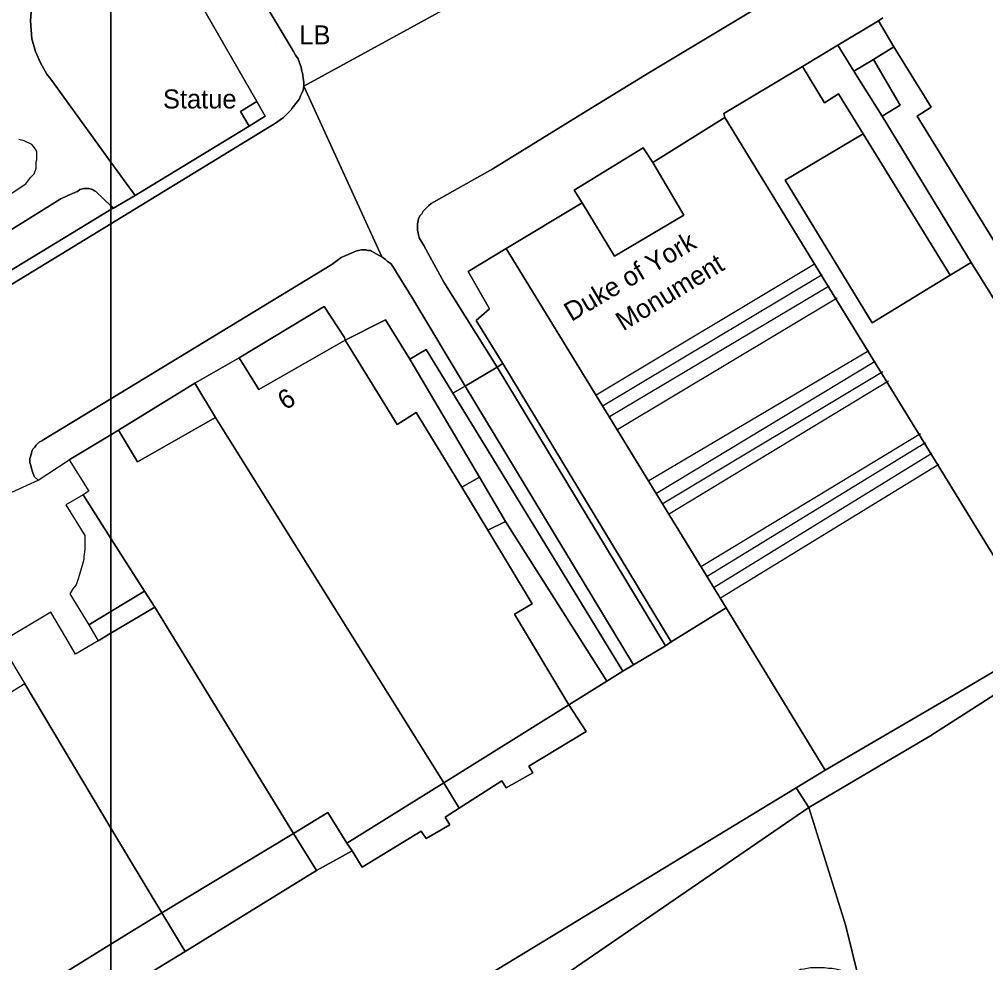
# Model space of a CAD drawing. Extents: x 529240 to 530363, y 179600 to 180767.
# Drawn here: x 529708.8 to 529784.9, y 180192.1 to 180266.5 of the extents above; entities that cross this region are included whole.
import ezdxf

# ---------------------------------------------------------------- set-up
doc = ezdxf.new("R2010")
doc.units = 0
for name, color, linetype in [('Building', 7, 'Continuous'), ('General surface', 7, 'Continuous'), ('Natural environment', 7, 'Continuous'), ('Path', 7, 'Continuous'), ('Road Or Track', 7, 'Continuous'), ('Roadside', 7, 'Continuous'), ('Structure', 7, 'Continuous'), ('Unclassified', 7, 'Continuous')]:
    doc.layers.add(name, color=color, linetype=linetype)

msp = doc.modelspace()

# ---------------------------------------------------------------- linework, layer by layer
at = {"layer": 'Building'}
for points in [[(529776.85, 180266.6), (529776.5, 180266.35), (529777.7, 180264.3), (529780.65, 180259.55), (529779.55, 180258.85), (529788.6, 180244.15)], [(529776.85, 180266.6), (529776.5, 180266.35)], [(529777.7, 180264.3), (529776.5, 180266.35)], [(529794, 180237.65), (529789.6, 180244.8), (529788.6, 180244.15), (529779.55, 180258.85), (529780.65, 180259.55), (529777.7, 180264.3)], [(529782.15, 180246.3), (529776, 180242.55), (529769.15, 180253.8), (529775.3, 180257.45)], [(529775.3, 180257.45), (529782.15, 180246.3)], [(529734.45, 180241.2), (529727.65, 180237.3), (529726.1, 180239.8)], [(529734.45, 180241.2), (529734.4, 180241.4)], [(529734.45, 180241.2), (529738.55, 180234.55), (529740.05, 180235.5), (529743.65, 180229.6)], [(529726.1, 180239.8), (529722.6, 180237.8)], [(529722.6, 180237.8), (529724.25, 180235.1)], [(529724.25, 180235.1), (529718.1, 180231.6), (529716.6, 180234.1)], [(529724.25, 180235.1), (529742.25, 180206.3)], [(529716.6, 180234.1), (529716, 180233.738)], [(529716, 180233.738), (529712.7, 180231.75)], [(529743.65, 180229.6), (529745.7, 180226.2)], [(529713.8, 180229), (529716, 180225.553)], [(529716, 180225.553), (529718.65, 180221.4)], [(529745.7, 180226.2), (529749.2, 180220.4), (529747.8, 180219.6), (529752.1, 180212.45)], [(529716, 180219.804), (529718.65, 180221.4)], [(529718.65, 180221.4), (529719.45, 180220.15)], [(529719.45, 180220.15), (529716, 180218.096)], [(529719.45, 180220.15), (529730.4, 180202.3)], [(529714.25, 180218.75), (529716, 180219.804)], [(529716, 180218.096), (529715, 180217.5)], [(529709.2, 180214.1), (529716, 180202.735)], [(529752.1, 180212.45), (529742.25, 180206.3)], [(529742.25, 180206.3), (529734.6, 180201.55)], [(529734.6, 180201.55), (529733.1, 180203.95), (529730.4, 180202.3)], [(529716, 180202.735), (529720, 180196.05)], [(529730.4, 180202.3), (529720, 180196.05)], [(529730.4, 180202.3), (529732.2, 180199.4)], [(529735, 180200.95), (529734.6, 180201.55)], [(529735, 180200.95), (529732.2, 180199.4)], [(529732.2, 180199.4), (529721.85, 180193)], [(529720, 180196.05), (529716, 180193.578)], [(529720, 180196.05), (529721.85, 180193)], [(529716, 180193.578), (529707.3, 180188.2)], [(529721.85, 180193), (529716, 180189.421)]]:
    msp.add_lwpolyline(points, dxfattribs=at)
for points in [[(529782.15, 180246.3), (529775.3, 180257.45), (529769.15, 180253.8), (529776, 180242.55)], [(529745.7, 180226.2), (529743.65, 180229.6), (529740.05, 180235.5), (529738.55, 180234.55), (529734.45, 180241.2), (529727.65, 180237.3), (529726.1, 180239.8), (529722.6, 180237.8), (529724.25, 180235.1), (529742.25, 180206.3), (529752.1, 180212.45), (529747.8, 180219.6), (529749.2, 180220.4)], [(529716, 180225.553), (529718.65, 180221.4), (529719.45, 180220.15), (529730.4, 180202.3), (529733.1, 180203.95), (529734.6, 180201.55), (529742.25, 180206.3), (529724.25, 180235.1), (529718.1, 180231.6), (529716.6, 180234.1), (529716, 180233.738)], [(529716, 180225.553), (529716, 180233.738), (529712.7, 180231.75), (529714.25, 180229.3), (529713.8, 180229)], [(529716, 180218.096), (529719.45, 180220.15), (529718.65, 180221.4), (529716, 180219.804)], [(529716, 180202.735), (529720, 180196.05), (529730.4, 180202.3), (529719.45, 180220.15), (529716, 180218.096)], [(529716, 180202.735), (529716, 180218.096), (529715, 180217.5), (529713.2, 180216.45), (529712.45, 180217.75), (529711.25, 180219.75), (529707.25, 180217.35), (529707.45, 180217.05), (529709.2, 180214.1)], [(529716, 180218.096), (529716, 180219.804), (529714.25, 180218.75), (529715, 180217.5)], [(529716, 180193.578), (529716, 180202.735), (529709.2, 180214.1), (529706.65, 180212.55), (529704.8, 180215.45), (529704.55, 180215.8), (529700.4, 180213.2), (529701.7, 180211.15), (529702.45, 180210), (529696.3, 180206.1), (529707.3, 180188.2)], [(529730.4, 180202.3), (529732.2, 180199.4), (529735, 180200.95), (529734.6, 180201.55), (529733.1, 180203.95)], [(529716, 180193.578), (529720, 180196.05), (529716, 180202.735)], [(529721.85, 180193), (529732.2, 180199.4), (529730.4, 180202.3), (529720, 180196.05)], [(529716, 180189.421), (529721.85, 180193), (529720, 180196.05), (529716, 180193.578)], [(529716, 180189.421), (529716, 180193.578), (529707.3, 180188.2), (529709.1, 180185.2)]]:
    msp.add_lwpolyline(points, close=True, dxfattribs=at)
at = {"layer": 'General surface'}
for points in [[(529776.5, 180266.35), (529773.3, 180264.45), (529774.55, 180262.4), (529776.1, 180263.3), (529777.7, 180264.3)], [(529775.3, 180257.45), (529782.15, 180246.3), (529783.8, 180247.3), (529776.8, 180258.85), (529774.55, 180262.4), (529773.3, 180264.45), (529770.5, 180262.75), (529772.25, 180259.9), (529773.35, 180260.6)], [(529795.1, 180235.6), (529794, 180237.65), (529789.6, 180244.8), (529788.6, 180244.15), (529779.55, 180258.85), (529780.65, 180259.55), (529777.7, 180264.3), (529776.1, 180263.3), (529778.2, 180259.7), (529776.8, 180258.85), (529783.8, 180247.3), (529790.55, 180236.45), (529792.15, 180237.3), (529793.8, 180234.85)], [(529776.1, 180263.3), (529774.55, 180262.4), (529776.8, 180258.85), (529778.2, 180259.7)], [(529734.45, 180241.2), (529734.4, 180241.4), (529732.8, 180243.85), (529726.1, 180239.8), (529727.65, 180237.3)], [(529737.65, 180242.8), (529734.45, 180241.2), (529738.55, 180234.55), (529740.05, 180235.5), (529743.65, 180229.6), (529745.05, 180230.4), (529739.55, 180239.7)], [(529743.93, 180237.57), (529757.2, 180215.6), (529759.7, 180217.1), (529746.45, 180239.07)], [(529722.6, 180237.8), (529716.6, 180234.1), (529718.1, 180231.6), (529724.25, 180235.1)], [(529747.1, 180226.9), (529745.05, 180230.4), (529743.65, 180229.6), (529745.7, 180226.2)], [(529716, 180219.804), (529716, 180225.553), (529713.8, 180229), (529712.45, 180228.2), (529713.95, 180225.8), (529713.95, 180224.7), (529713.85, 180224.15), (529713.85, 180223.9), (529713.55, 180222.8), (529713.4, 180222.3), (529713.25, 180221.9), (529713, 180221.6), (529712.75, 180221.2), (529714.25, 180218.75)], [(529745.7, 180226.2), (529749.2, 180220.4), (529747.8, 180219.6), (529752.1, 180212.45), (529755.1, 180214.3), (529747.1, 180226.9)], [(529716, 180219.804), (529718.65, 180221.4), (529716, 180225.553)], [(529772.3, 180207.3), (529770, 180205.9), (529771, 180204.35), (529780.55, 180209.98), (529792.04, 180217.33), (529795.6, 180213.47), (529800.09, 180209.09), (529800, 180209.4), (529799.85, 180209.7), (529799.55, 180210.6), (529799.5, 180210.85), (529799.5, 180211.55), (529799.55, 180211.75), (529799.6, 180212), (529799.8, 180212.5), (529805.55, 180216.7), (529801.05, 180224.3), (529798.35, 180222.65), (529789.7, 180217.5), (529782.39, 180213.19)], [(529752.1, 180212.45), (529742.25, 180206.3), (529743.45, 180204.3), (529746.8, 180206.45), (529747.15, 180205.9), (529749.25, 180207.1), (529748.95, 180207.6), (529753.45, 180210.35)], [(529716, 180166.623), (529771, 180204.35), (529770, 180205.9), (529739.62, 180187.44), (529729.1, 180181.05), (529716.27, 180173.25), (529716, 180173.086)], [(529743.45, 180204.3), (529742.25, 180206.3), (529734.6, 180201.55), (529735, 180200.95), (529735.8, 180199.65), (529740.45, 180202.5), (529740.85, 180201.9), (529742.7, 180203), (529742.35, 180203.6)], [(529716, 180166.623), (529716, 180154.06), (529749.3, 180177.15), (529770.35, 180191.6), (529770.65, 180191.65), (529771.15, 180191.75), (529772.25, 180191.75), (529772.55, 180191.7), (529772.85, 180191.7), (529773.15, 180191.65), (529773.45, 180191.55), (529773.55, 180191.5), (529773.85, 180191.4), (529774.35, 180191.1), (529774.99, 180190.74), (529773.91, 180195.12), (529771, 180204.35)]]:
    msp.add_lwpolyline(points, close=True, dxfattribs=at)
for points in [[(529790.55, 180236.45), (529783.8, 180247.3), (529782.15, 180246.3), (529776, 180242.55), (529769.15, 180253.8), (529775.3, 180257.45), (529773.35, 180260.6), (529772.25, 180259.9), (529770.5, 180262.75), (529764.3, 180259.05), (529764.4, 180258.75), (529773.15, 180244.45), (529781.2, 180231.3), (529789.7, 180217.5)], [(529739.62, 180187.44), (529770, 180205.9), (529772.3, 180207.3), (529764.5, 180220.1), (529760.15, 180217.4), (529759.7, 180217.1), (529757.2, 180215.6), (529756.35, 180215.1), (529755.1, 180214.3), (529752.1, 180212.45), (529753.45, 180210.35), (529748.95, 180207.6), (529749.25, 180207.1), (529747.15, 180205.9), (529746.8, 180206.45), (529743.45, 180204.3), (529742.35, 180203.6), (529742.7, 180203), (529740.85, 180201.9), (529740.45, 180202.5), (529735.8, 180199.65), (529735, 180200.95), (529732.2, 180199.4), (529721.85, 180193), (529716, 180189.421)]]:
    msp.add_lwpolyline(points, dxfattribs=at)
at = {"layer": 'Natural environment'}
for points in [[(529709.7, 180267.05), (529709.65, 180266.35), (529709.75, 180264.95), (529710.05, 180263.95), (529710.45, 180263.05), (529710.95, 180262.15), (529711.25, 180261.75), (529716, 180255.214), (529716, 180275.918)], [(529686.9, 180233.8), (529716, 180251.478), (529716, 180251.786), (529714.8, 180252.9), (529714.7, 180252.95), (529714.55, 180253.05), (529714.25, 180253.15), (529713.85, 180253.15), (529713.55, 180253.05), (529713.35, 180252.9), (529713.2, 180252.85), (529713.1, 180252.8), (529712.6, 180252.6), (529712, 180252.3), (529709.05, 180250.45), (529687, 180236.95)]]:
    msp.add_lwpolyline(points, dxfattribs=at)
for points in [[(529716, 180255.214), (529717.9, 180252.6), (529726.9, 180258.05), (529726.2, 180259.2), (529727.5, 180260), (529718.9, 180274.95), (529717.2, 180273.95), (529716, 180275.918)], [(529716, 180251.478), (529716.2, 180251.6), (529716, 180251.786)]]:
    msp.add_lwpolyline(points, close=True, dxfattribs=at)
at = {"layer": 'Path'}
for points in [[(529687, 180236.95), (529709.05, 180250.45), (529712, 180252.3), (529712.6, 180252.6), (529713.1, 180252.8), (529713.2, 180252.85), (529713.35, 180252.9), (529713.55, 180253.05), (529713.85, 180253.15), (529714.25, 180253.15), (529714.55, 180253.05), (529714.7, 180252.95), (529714.8, 180252.9), (529716, 180251.786), (529716, 180255.214), (529711.25, 180261.75), (529710.95, 180262.15), (529710.45, 180263.05), (529710.05, 180263.95), (529709.75, 180264.95), (529709.65, 180266.35), (529709.7, 180267.05)], [(529706.6, 180251.75), (529709.3, 180253.5), (529709.65, 180254), (529709.95, 180254.3), (529710.1, 180254.75), (529710.1, 180255.25), (529710.15, 180255.4), (529710.15, 180256), (529710.1, 180256.15), (529709.9, 180256.45), (529709.75, 180256.6), (529709.15, 180256.9), (529708.75, 180257)]]:
    msp.add_lwpolyline(points, dxfattribs=at)
for points in [[(529716, 180251.786), (529716.2, 180251.6), (529717.9, 180252.6), (529716, 180255.214)], [(529746.45, 180239.07), (529759.7, 180217.1), (529760.15, 180217.4), (529746.9, 180239.35)], [(529742.95, 180237), (529746.45, 180231.3), (529756.35, 180215.1), (529757.2, 180215.6), (529743.93, 180237.57)]]:
    msp.add_lwpolyline(points, close=True, dxfattribs=at)
at = {"layer": 'Road Or Track'}
for points in [[(529716, 180288.42), (529716.45, 180287.5), (529717.65, 180285.2), (529730.2, 180264.25), (529730.4, 180263.95), (529730.55, 180263.65), (529730.75, 180263.35), (529730.85, 180263.05), (529731, 180262.7), (529731.05, 180262.35), (529731.1, 180262.25), (529731.15, 180261.85), (529731.2, 180261.5), (529731.2, 180261.2), (529746.35, 180269.5), (529746.2, 180269.55), (529746, 180269.65), (529745.85, 180269.8), (529745.75, 180269.95), (529732.4, 180292.4), (529731.05, 180291.55), (529727.65, 180297.5), (529728.85, 180298.25), (529716, 180320.312)], [(529716, 180236.572), (529733.4, 180247.15), (529734.15, 180247.7), (529735.3, 180248.2), (529735.5, 180248.25), (529735.75, 180248.3), (529736.1, 180248.3), (529736.25, 180248.25), (529736.45, 180248.25), (529736.55, 180248.2), (529737.1, 180247.9), (529737.35, 180247.75), (529731.2, 180261.2), (529731.15, 180260.9), (529731.05, 180260.65), (529730.95, 180260.45), (529730.85, 180260.2), (529730.4, 180259.6), (529730.25, 180259.45), (529730.2, 180259.35), (529729.6, 180258.75), (529728.9, 180258.25), (529728.5, 180258), (529716, 180250.359)]]:
    msp.add_lwpolyline(points, close=True, dxfattribs=at)
for points in [[(529716, 180288.42), (529716.45, 180287.5), (529717.65, 180285.2), (529730.2, 180264.25), (529730.4, 180263.95), (529730.55, 180263.65), (529730.75, 180263.35), (529730.85, 180263.05), (529731, 180262.7), (529731.05, 180262.35), (529731.1, 180262.25), (529731.15, 180261.85), (529731.2, 180261.5), (529731.2, 180261.2)], [(529746.35, 180269.5), (529731.2, 180261.2), (529737.35, 180247.75), (529737.65, 180247.55), (529737.8, 180247.4), (529738.1, 180247.2), (529739.8, 180244.45), (529743.93, 180237.57), (529746.45, 180239.07), (529742.25, 180245.75), (529740.65, 180248.65), (529740.3, 180249.25), (529740.15, 180249.85), (529740.15, 180250.35), (529740.25, 180250.75), (529740.35, 180251), (529740.5, 180251.15), (529740.6, 180251.35), (529741.05, 180251.8), (529741.25, 180251.95), (529746.1, 180254.7), (529752.14, 180258.41), (529753.52, 180259.26), (529758.4, 180262.25), (529767.85, 180267.93)], [(529767.85, 180267.93), (529758.4, 180262.25), (529753.52, 180259.26), (529752.14, 180258.41), (529746.1, 180254.7), (529741.25, 180251.95), (529741.05, 180251.8), (529740.6, 180251.35), (529740.5, 180251.15), (529740.35, 180251), (529740.25, 180250.75), (529740.15, 180250.35), (529740.15, 180249.85), (529740.3, 180249.25), (529740.65, 180248.65), (529742.25, 180245.75)], [(529731.2, 180261.2), (529731.15, 180260.9), (529731.05, 180260.65), (529730.95, 180260.45), (529730.85, 180260.2), (529730.4, 180259.6), (529730.25, 180259.45), (529730.2, 180259.35), (529729.6, 180258.75), (529728.9, 180258.25), (529728.5, 180258), (529716, 180250.359)], [(529716, 180250.359), (529712.55, 180248.25), (529676.85, 180226.5), (529651.05, 180210.85), (529650.75, 180210.55), (529650.55, 180210.45), (529650.3, 180210.35), (529650.2, 180210.3), (529649.95, 180210.25), (529649.75, 180210.15), (529649.5, 180210.15)], [(529706.95, 180228.65), (529710.25, 180230.15), (529709.95, 180230.45), (529709.8, 180230.9), (529709.75, 180231), (529709.65, 180231.4), (529709.6, 180231.55), (529709.6, 180231.85), (529709.65, 180232), (529709.7, 180232.2), (529709.8, 180232.5), (529709.85, 180232.6), (529710, 180232.75), (529710.1, 180232.9), (529710.35, 180233.15), (529710.55, 180233.25), (529710.7, 180233.35), (529716, 180236.572), (529716, 180250.359), (529712.55, 180248.25), (529676.85, 180226.5)], [(529737.35, 180247.75), (529737.1, 180247.9), (529736.55, 180248.2), (529736.45, 180248.25), (529736.25, 180248.25), (529736.1, 180248.3), (529735.75, 180248.3), (529735.5, 180248.25), (529735.3, 180248.2), (529734.15, 180247.7), (529733.4, 180247.15), (529716, 180236.572)], [(529739.8, 180244.45), (529738.1, 180247.2), (529737.8, 180247.4), (529737.65, 180247.55), (529737.35, 180247.75)], [(529716, 180236.572), (529710.7, 180233.35), (529710.55, 180233.25), (529710.35, 180233.15), (529710.1, 180232.9), (529710, 180232.75), (529709.85, 180232.6), (529709.8, 180232.5), (529709.7, 180232.2), (529709.65, 180232), (529709.6, 180231.85), (529709.6, 180231.55), (529709.65, 180231.4), (529709.75, 180231), (529709.8, 180230.9), (529709.95, 180230.45), (529710.25, 180230.15)], [(529792.04, 180217.33), (529780.55, 180209.98), (529771, 180204.35), (529773.91, 180195.12), (529774.99, 180190.74)], [(529771, 180204.35), (529780.55, 180209.98), (529792.04, 180217.33), (529795.6, 180213.47), (529800.09, 180209.09)], [(529774.99, 180190.74), (529773.91, 180195.12), (529771, 180204.35)]]:
    msp.add_lwpolyline(points, dxfattribs=at)
at = {"layer": 'Roadside'}
for points in [[(529718.9, 180274.95), (529727.5, 180260), (529728.15, 180258.85), (529726.9, 180258.05), (529717.9, 180252.6), (529716.2, 180251.6), (529716, 180251.478), (529716, 180250.359), (529728.5, 180258), (529728.9, 180258.25), (529729.6, 180258.75), (529730.2, 180259.35), (529730.25, 180259.45), (529730.4, 180259.6), (529730.85, 180260.2), (529730.95, 180260.45), (529731.05, 180260.65), (529731.15, 180260.9), (529731.2, 180261.2), (529731.2, 180261.5), (529731.15, 180261.85), (529731.1, 180262.25), (529731.05, 180262.35), (529731, 180262.7), (529730.85, 180263.05), (529730.75, 180263.35), (529730.55, 180263.65), (529730.4, 180263.95), (529730.2, 180264.25), (529717.65, 180285.2)], [(529767.85, 180267.93), (529758.4, 180262.25), (529753.52, 180259.26), (529752.14, 180258.41), (529746.1, 180254.7), (529741.25, 180251.95), (529741.05, 180251.8), (529740.6, 180251.35), (529740.5, 180251.15), (529740.35, 180251), (529740.25, 180250.75), (529740.15, 180250.35), (529740.15, 180249.85), (529740.3, 180249.25), (529740.65, 180248.65), (529742.25, 180245.75), (529746.45, 180239.07), (529746.9, 180239.35), (529744.8, 180242.75), (529745.85, 180243.65), (529744.15, 180246.6), (529747.15, 180248.4), (529753.15, 180252), (529752.5, 180253), (529757.95, 180256.35), (529758.7, 180255.2), (529764.4, 180258.75), (529764.3, 180259.05), (529770.5, 180262.75), (529773.3, 180264.45), (529776.5, 180266.35), (529776.85, 180266.6)], [(529651.05, 180210.85), (529676.85, 180226.5), (529712.55, 180248.25), (529716, 180250.359), (529716, 180251.478), (529686.9, 180233.8), (529685.65, 180233.05), (529654.9, 180214.4)]]:
    msp.add_lwpolyline(points, dxfattribs=at)
for points in [[(529746.9, 180239.35), (529760.15, 180217.4), (529764.5, 180220.1), (529747.15, 180248.4), (529744.15, 180246.6), (529745.85, 180243.65), (529744.8, 180242.75)], [(529716, 180233.738), (529716.6, 180234.1), (529722.6, 180237.8), (529726.1, 180239.8), (529732.8, 180243.85), (529734.4, 180241.4), (529734.45, 180241.2), (529737.65, 180242.8), (529739.55, 180239.7), (529740.85, 180240.45), (529742.95, 180237), (529743.93, 180237.57), (529739.8, 180244.45), (529738.1, 180247.2), (529737.8, 180247.4), (529737.65, 180247.55), (529737.35, 180247.75), (529737.1, 180247.9), (529736.55, 180248.2), (529736.45, 180248.25), (529736.25, 180248.25), (529736.1, 180248.3), (529735.75, 180248.3), (529735.5, 180248.25), (529735.3, 180248.2), (529734.15, 180247.7), (529733.4, 180247.15), (529716, 180236.572)], [(529745.05, 180230.4), (529747.1, 180226.9), (529755.1, 180214.3), (529756.35, 180215.1), (529746.45, 180231.3), (529742.95, 180237), (529740.85, 180240.45), (529739.55, 180239.7)], [(529716, 180233.738), (529716, 180236.572), (529710.7, 180233.35), (529710.55, 180233.25), (529710.35, 180233.15), (529710.1, 180232.9), (529710, 180232.75), (529709.85, 180232.6), (529709.8, 180232.5), (529709.7, 180232.2), (529709.65, 180232), (529709.6, 180231.85), (529709.6, 180231.55), (529709.65, 180231.4), (529709.75, 180231), (529709.8, 180230.9), (529709.95, 180230.45), (529710.25, 180230.15), (529710.95, 180230.6), (529712.7, 180231.75)]]:
    msp.add_lwpolyline(points, close=True, dxfattribs=at)
at = {"layer": 'Structure'}
msp.add_line((529729, 180264.3), (529729, 180264.3), dxfattribs=at)
for points in [[(529726.9, 180258.05), (529728.15, 180258.85), (529727.5, 180260), (529726.2, 180259.2)], [(529789.7, 180217.5), (529781.2, 180231.3), (529773.15, 180244.45), (529764.4, 180258.75), (529758.7, 180255.2), (529761.15, 180251.05), (529755.7, 180247.8), (529753.15, 180252), (529747.15, 180248.4), (529764.5, 180220.1), (529772.3, 180207.3), (529782.39, 180213.19)], [(529758.7, 180255.2), (529757.95, 180256.35), (529752.5, 180253), (529753.15, 180252), (529755.7, 180247.8), (529761.15, 180251.05)]]:
    msp.add_lwpolyline(points, close=True, dxfattribs=at)
at = {"layer": 'Unclassified'}
for points in [[(529727.5, 180260), (529718.9, 180274.95)], [(529746.35, 180269.5), (529731.2, 180261.2)], [(529709.7, 180267.05), (529709.65, 180266.35), (529709.75, 180264.95), (529710.05, 180263.95), (529710.45, 180263.05), (529710.95, 180262.15), (529711.25, 180261.75), (529716, 180255.214)], [(529776.5, 180266.35), (529773.3, 180264.45)], [(529773.3, 180264.45), (529770.5, 180262.75)], [(529774.55, 180262.4), (529773.3, 180264.45)], [(529776.1, 180263.3), (529777.7, 180264.3)], [(529774.55, 180262.4), (529776.1, 180263.3)], [(529776.1, 180263.3), (529778.2, 180259.7), (529776.8, 180258.85)], [(529770.5, 180262.75), (529764.3, 180259.05), (529764.4, 180258.75)], [(529770.5, 180262.75), (529772.25, 180259.9), (529773.35, 180260.6), (529775.3, 180257.45)], [(529776.8, 180258.85), (529774.55, 180262.4)], [(529737.35, 180247.75), (529731.2, 180261.2)], [(529727.5, 180260), (529726.2, 180259.2), (529726.9, 180258.05)], [(529726.9, 180258.05), (529728.15, 180258.85), (529727.5, 180260)], [(529764.4, 180258.75), (529758.7, 180255.2)], [(529789.7, 180217.5), (529781.2, 180231.3), (529773.15, 180244.45), (529764.4, 180258.75)], [(529783.8, 180247.3), (529776.8, 180258.85)], [(529717.9, 180252.6), (529726.9, 180258.05)], [(529758.7, 180255.2), (529757.95, 180256.35), (529752.5, 180253), (529753.15, 180252)], [(529716, 180255.214), (529717.9, 180252.6)], [(529753.15, 180252), (529755.7, 180247.8), (529761.15, 180251.05), (529758.7, 180255.2)], [(529716, 180251.786), (529714.8, 180252.9), (529714.7, 180252.95), (529714.55, 180253.05), (529714.25, 180253.15), (529713.85, 180253.15), (529713.55, 180253.05), (529713.35, 180252.9), (529713.2, 180252.85), (529713.1, 180252.8), (529712.6, 180252.6), (529712, 180252.3), (529709.05, 180250.45), (529687, 180236.95)], [(529716.2, 180251.6), (529717.9, 180252.6)], [(529686.9, 180233.8), (529716, 180251.478)], [(529716.2, 180251.6), (529716, 180251.786)], [(529716, 180251.478), (529716.2, 180251.6)], [(529753.15, 180252), (529747.15, 180248.4)], [(529747.15, 180248.4), (529744.15, 180246.6)], [(529764.5, 180220.1), (529747.15, 180248.4)], [(529771.5, 180247.2), (529754.25, 180236.85)], [(529782.15, 180246.3), (529783.8, 180247.3)], [(529795.1, 180235.6), (529793.8, 180234.85), (529792.15, 180237.3), (529790.55, 180236.45), (529783.8, 180247.3)], [(529744.15, 180246.6), (529745.85, 180243.65), (529744.8, 180242.75), (529746.9, 180239.35)], [(529772.05, 180246.35), (529754.8, 180236)], [(529742.25, 180245.75), (529746.45, 180239.07)], [(529772.6, 180245.45), (529755.3, 180235.15)], [(529734.4, 180241.4), (529732.8, 180243.85), (529726.1, 180239.8)], [(529743.93, 180237.57), (529739.8, 180244.45)], [(529773.25, 180244.5), (529755.95, 180234.15)], [(529737.65, 180242.8), (529734.45, 180241.2)], [(529737.65, 180242.8), (529739.55, 180239.7)], [(529739.55, 180239.7), (529740.85, 180240.45), (529742.95, 180237)], [(529775.75, 180240.35), (529758.4, 180230.1)], [(529739.55, 180239.7), (529745.05, 180230.4)], [(529746.45, 180239.07), (529746.9, 180239.35)], [(529746.9, 180239.35), (529760.15, 180217.4)], [(529776.25, 180239.5), (529759, 180229.1)], [(529743.93, 180237.57), (529746.45, 180239.07)], [(529746.45, 180239.07), (529759.7, 180217.1)], [(529776.85, 180238.7), (529759.45, 180228.25)], [(529722.6, 180237.8), (529716.6, 180234.1)], [(529777.3, 180237.95), (529759.95, 180227.45)], [(529742.95, 180237), (529743.93, 180237.57)], [(529742.95, 180237), (529746.45, 180231.3), (529756.35, 180215.1)], [(529757.2, 180215.6), (529743.93, 180237.57)], [(529779.8, 180233.8), (529762.55, 180223.35)], [(529780.2, 180233.1), (529763, 180222.55)], [(529780.7, 180232.25), (529763.55, 180221.7)], [(529781.25, 180231.4), (529764.05, 180220.85)], [(529743.65, 180229.6), (529745.05, 180230.4)], [(529745.05, 180230.4), (529747.1, 180226.9)], [(529745.7, 180226.2), (529747.1, 180226.9)], [(529747.1, 180226.9), (529755.1, 180214.3)], [(529764.5, 180220.1), (529760.15, 180217.4)], [(529772.3, 180207.3), (529764.5, 180220.1)], [(529760.15, 180217.4), (529759.7, 180217.1)], [(529772.3, 180207.3), (529782.39, 180213.19), (529789.7, 180217.5)], [(529759.7, 180217.1), (529757.2, 180215.6)], [(529757.2, 180215.6), (529756.35, 180215.1)], [(529756.35, 180215.1), (529755.1, 180214.3)], [(529755.1, 180214.3), (529752.1, 180212.45)], [(529752.1, 180212.45), (529753.45, 180210.35), (529748.95, 180207.6), (529749.25, 180207.1), (529747.15, 180205.9), (529746.8, 180206.45), (529743.45, 180204.3)], [(529770, 180205.9), (529772.3, 180207.3)], [(529716, 180173.086), (529716.27, 180173.25), (529729.1, 180181.05), (529739.62, 180187.44), (529770, 180205.9)], [(529742.25, 180206.3), (529743.45, 180204.3)], [(529770, 180205.9), (529771, 180204.35)], [(529771, 180204.35), (529716, 180166.623)], [(529743.45, 180204.3), (529742.35, 180203.6), (529742.7, 180203), (529740.85, 180201.9), (529740.45, 180202.5), (529735.8, 180199.65), (529735, 180200.95)]]:
    msp.add_lwpolyline(points, dxfattribs=at)

# ---------------------------------------------------------------- texts
at = {"layer": 'Structure'}
for s, p in [('LB', (529730.85, 180264.5)), ('Statue', (529720.1, 180259.45))]:
    msp.add_text(s, height=1.5, dxfattribs=at).set_placement(p)
for s, rotation, p in [('Duke of York', 30.6, (529752.29, 180242.62)), ('Monument', 31.3, (529756.38, 180241.87))]:
    msp.add_text(s, height=1.5, rotation=rotation, dxfattribs=at).set_placement(p)
at = {"layer": 'Unclassified'}
msp.add_text('9', height=1.5, rotation=212.1, dxfattribs=at).set_placement((529729.9, 180237.5))

doc.saveas('drawing.dxf')
